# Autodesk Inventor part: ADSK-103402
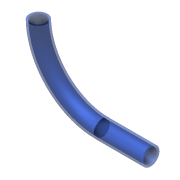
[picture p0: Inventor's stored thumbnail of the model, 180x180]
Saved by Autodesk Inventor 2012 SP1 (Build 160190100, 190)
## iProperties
Shininess: 20.0
Created: 2001-04
Part Number: ADSK-103402
Document SubType Name: Modeling
Designer: Administrator
Stock Number: ADSK-103402
Density: 1 g/cm^3
Material: Default
Density: 0.0
Volumn: 0.0
Area: 0.0
PropertySet Name: Model Information
Control State: 0
Master: False
Checked Out: False
Author: Administrator
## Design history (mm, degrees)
sketch "Sketch1"
  geometry: L1 (13.011, 0)-(-12.389, 0); A1 r 34.075 centre (-12.389, 34.075) between (-46.457, 33.383) and (-12.389, 0)
  constraints: 2 end point, 2 point on circle, 1 centre point, 1 horizontal, 1 tangent
workplane "Work Plane2"
  workpoint "Work Point1"
sketch "Sketch2"
  geometry: C1 r 4.763 at (0, 0); C2 r 3.81 at (0, 0)
  constraints: 2 centre point
  dimensions: "d3" = 9.525 diameter of C1; "d4" = 7.62 diameter of C2
sweep "Sweep1" sketch "Sketch2" dims "d5" = 0
body "Solid1"
workplane "Work Plane1"
other parameters: "d2" = 0
